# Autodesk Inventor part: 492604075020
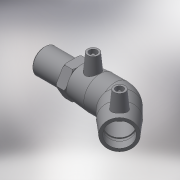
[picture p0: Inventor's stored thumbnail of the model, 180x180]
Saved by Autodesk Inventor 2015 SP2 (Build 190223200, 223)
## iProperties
Created: 2017-06
Part Number: 492604075020
Material: Generic
Description: PLASSON 45° ELBOW TRANSITION MALE 75-2"
Document SubType Name: Modeling
Designer: KIM
Mass: 809.857 g
Surface Area: 1232.77 cm^2
Volume: 809.857 cm^3
Density: 1 g/cm^3
Appearance: Default
Author: KIM
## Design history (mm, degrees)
derived "492604.ipt"
feature "Solid1::492604.ipt"
tag "TaggingFeature1"
body "Solid1"
other parameters: "d2" = 98, "d4" = 45, "d5" = 88.2, "d8" = 168 deg, "d10" = 28.4, "d11" = 9.46667, "d29" = 62, "d30" = 15, "d31" = 63, "d34" = 5 deg, "d41" = 4, "d42" = 14, "d43" = 0, "d49" = 75, "d50" = 48.75, "d51" = 28.4, "d52" = 73.13, "d54" = 135 deg, "d86" = 44.1, "d87" = 135 deg, "d90" = 71, "d91" = 0, "d92" = 71, "d93" = 0, "d101" = 3, "d102" = 0, "d107" = 0.1, "d108" = 59, "d109" = 59.614, "d110" = 41, "d111" = 10.25, "d112" = 98, "d113" = 41.7298, "d114" = 36.9, "d116" = 2.94, "d122" = 0, "d123" = 2.9807, "d_" = 75, "L_" = 221, "L_1" = 71, "D_" = 59, "A_" = 62, "d_2" = 12, "L_2" = 41, "R_" = 59.614, "D_1" = 98
